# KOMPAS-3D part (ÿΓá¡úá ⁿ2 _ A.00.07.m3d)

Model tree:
1. Эскиз:1
2. Операция выдавливания:1
     Расстояние 1 = 130
3. Эскиз:2
4. Операция выдавливания:2
     Расстояние 1 = 4
5. Эскиз:3
6. Операция выдавливания:3
     Расстояние 1 = 42
7. Скругление:1
     Радиус = 6
8. Скругление:3
     Радиус = 15
9. Эскиз:4
10. Вырезать элемент выдавливания:1
     Расстояние 1 = 50
11. Скругление:4  (labels: A.00.07; SYSTEM_PROPERTY_ADDITIONAL_FOR:5.000000)
     Радиус = 3

Referenced files in C:\Program Files (x86)\ASCON\KOMPAS-3D V15\Libs\PartLib\DATA\vault\Methods\Kompas\3D\: PLib_Nut_OST92_900.m3d
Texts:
  Штанга №2
  Гайка М10-6H ГОСТ 2524-70
  bcut1
  hole1
  hcut1
  hole2
  cut1
  (-) Гайка М10-6H ГОСТ 2524-70
  ГОСТ 2524-70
